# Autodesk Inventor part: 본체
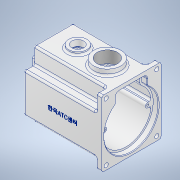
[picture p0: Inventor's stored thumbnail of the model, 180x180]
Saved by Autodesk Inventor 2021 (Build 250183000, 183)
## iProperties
Created: 2022-08
Part Number: 본체
Material: 알루미늄 6061
Document SubType Name: Modeling
Designer: Owner
Density: 2.7 g/cm^3
Appearance: 알루미늄 - 평지
Mass: 1404.44 g
Surface Area: 1171.86 cm^2
Volume: 520.162 cm^3
Author: Owner
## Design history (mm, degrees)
sketch "스케치1"
  geometry: L1 (-55, 49)-(55, 49); L2 (55, 49)-(55, -49); L3 (55, -49)-(-55, -49); L4 (-55, -49)-(-55, 49); L5 (-55, 49)-(55, -49); L6 (55, 49)-(-55, -49); 1 further point
  constraints: 12 end point, 2 midpoint, 2 parallel, 1 horizontal, 1 perpendicular
  dimensions: "d0" = 98 distance of L1.end L2.end; "d1" = 110 distance of L1.start L1.end
extrude "돌출1" new body sketch "스케치1" distance "d2" = 10; taper "d3" = 0 deg
sketch "스케치2"
  geometry: L1 (-49, 55)-(-49, -55) reference; L2 (-49, -55)-(49, -55) reference; L3 (49, -55)-(49, 55) reference; L4 (49, 55)-(-49, 55) reference; L5 (-33, -55)-(33, -55); L6 (33, -55)-(33, -38); L7 (33, 55)-(-33, 55); L8 (-33, 55)-(-33, 28); L9 (-33, -55)-(33, 55); L10 (33, -55)-(-33, 55); L11 (-49, -38)-(-33, -38); L12 (49, -38)-(49, 28); L13 (49, 28)-(33, 28); L14 (-49, 28)-(-49, -38); L15 (-49, -38)-(49, 28); L16 (49, -38)-(-49, 28); L17 (-33, 28)-(-49, 28); L18 (33, 28)-(-33, 28); L19 (-33, -38)-(-33, -55); L20 (33, -38)-(49, -38); L21 (-33, 28)-(-33, -38); L22 (33, 28)-(33, 55); L23 (33, -38)-(33, 28); L24 (-33, -38)-(33, -38); 11 further points
  constraints: 40 end point, 20 parallel, 7 midpoint, 6 perpendicular, 4 horizontal, 2 point on line
  dimensions: "d4" = 66 distance of L7.start L7.end; "d6" = 17 distance between parallel lines of L2 L11; "d7" = 27 distance between parallel lines of L4 L13
extrude "돌출2" join sketch "스케치2" distance "d8" = 120; taper "d9" = 0 deg
sketch "스케치4"
  geometry: L1 (-49, -55)-(49, -55) reference; L2 (-23, 30.143)-(-23, 45); L3 (-23, 45)-(23, 45); L4 (23, 45)-(23, 30.143); L5 (0, 0)-(0, 19.376); A1 r 42 centre (0, -5) between (-23, 30.143) and (23, 30.143)
  constraints: 8 end point, 2 perpendicular, 2 point on circle, 2 vertical, 1 centre point, 1 vertical alignment, 1 other
  dimensions: "d14" = 50 distance from line of L1 A1.centre; "d15" = 46 distance of L2.end L3.end; "d16" = 50 distance from line of A1.centre L3; "d17" = 84 diameter of A1
extrude "돌출4" cut sketch "스케치4" distance "d18" = 121; taper "d19" = 0 deg
fillet "모깎기1" dims "d20" = 6
sketch "스케치5"
  geometry: L1 (-23, 33.249)-(-23, 45) reference; L2 (-23, 45)-(23, 45) reference; L3 (23, 45)-(23, 33.249) reference; L4 (-26, 48)-(-26, 33.249); L5 (26, 33.249)-(26, 48); L6 (26, 48)-(-26, 48); A1 r 6 centre (29, 33.249) between (23, 33.249) and (25.375, 28.468) reference; A2 r 42 centre (0, -5) between (-25.375, 28.468) and (25.375, 28.468) reference; A3 r 6 centre (-29, 33.249) between (-25.375, 28.468) and (-23, 33.249) reference; A4 r 3 centre (-29, 33.249) between (-27.187, 30.859) and (-26, 33.249); A5 r 45 centre (0, -5) between (-27.187, 30.859) and (27.188, 30.859); A6 r 3 centre (29, 33.249) between (26, 33.249) and (27.188, 30.859); 1 further point
  constraints: 6 end point, 6 point on circle, 3 centre point, 5 other
  dimensions: "d21" = 3 distance between parallel lines of L1 L4
extrude "돌출5" cut sketch "스케치5" distance "d22" = 9; taper "d23" = 0 deg
sketch "스케치6"
  geometry: A1 r 42 centre (0, -5) between (-25.375, 28.468) and (25.375, 28.468) reference; A2 r 15 centre (0, -25) between (-8.978, -12.984) and (8.978, -12.984); A3 r 21 centre (0, 6) between (8.978, -12.984) and (-8.978, -12.984); 1 further point
  constraints: 4 point on circle, 2 centre point, 2 vertical alignment
  dimensions: "d24" = 30 diameter of A2; "d25" = 20 distance of A2.centre A1.centre; "d26" = 42 diameter of A3; "d27" = 11 distance of A1.centre A3.centre
extrude "돌출6" join sketch "스케치6" distance "d28" = 7; taper "d29" = 0 deg
sketch "스케치8"
  geometry: A1 r 15 centre (0, -25) between (-8.978, -12.984) and (8.978, -12.984) reference; 2 further points
  constraints: 1 coincident
hole "구멍1" sketch "스케치8" at (0, -25) diameter "d30" = 19; stored, may be unused: countersink angle "d34" = 90 deg, drill point angle "d36" = 0 deg; dims "d31" = 12, "d32" = 22, "d33" = 7, "d35" = 10
sketch "스케치10"
  geometry: A1 r 21 centre (0, 6) between (8.978, -12.984) and (-8.978, -12.984) reference; 2 further points
  constraints: 1 coincident
hole "구멍3" sketch "스케치10" at (0, 6) diameter "d44" = 35; stored, may be unused: countersink angle "d48" = 90 deg, drill point angle "d50" = 0 deg; dims "d45" = 12, "d46" = 32, "d47" = 8.3, "d49" = 10
sketch "스케치11"
  geometry: L1 (0, -5)-(36, -5); L2 (0, -5)-(-36, -5); L3 (-35.777, -1)-(-41.809, -1); L4 (-35.777, -9)-(-41.809, -9); L5 (35.777, -1)-(41.809, -1); L6 (35.777, -9)-(41.809, -9); A1 r 42 centre (0, -5) between (-25.375, 28.468) and (25.375, 28.468) reference; A2 r 45 centre (0, -5) between (-27.187, 30.859) and (27.188, 30.859) reference; A3 r 36 centre (0, -5) between (36, -5) and (-36, -5); A4 r 4 centre (36, -5) between (36, -1) and (36, -9); A5 r 4 centre (-36, -5) between (-36, -9) and (-36, -1); 1 further point
  constraints: 14 point on circle, 12 end point, 5 point on line, 4 tangent, 3 centre point, 3 coincident, 3 horizontal, 2 parallel
  dimensions: "d51" = 72 diameter of A3; "d52" = 8 diameter of A5; "d53" = 8 diameter of A4
extrude "돌출7" join sketch "스케치11" stored distance "d54" = 121; taper "d55" = 0 deg
sketch "스케치12"
  geometry: A1 r 4 centre (36, -5) between (36, -1) and (36, -9) reference; 2 further points
  constraints: 1 coincident
hole "구멍4" sketch "스케치12" at (36, -5) diameter "d56" = 3.45873; stored, may be unused: countersink angle "d60" = 90 deg, drill point angle "d62" = 118 deg; dims "d57" = 7, "d58" = 32, "d59" = 8.3, "d61" = 9
sketch "스케치13"
  geometry: A1 r 4 centre (-36, -5) between (-36, -9) and (-36, -1) reference; 2 further points
  constraints: 1 coincident
hole "구멍5" sketch "스케치13" at (-36, -5) diameter "d63" = 3.45873; stored, may be unused: countersink angle "d67" = 90 deg, drill point angle "d69" = 118 deg; dims "d64" = 7, "d65" = 32, "d66" = 8.3, "d68" = 9
sketch "스케치15"
  geometry: L1 (-27, -21)-(27, -21); L2 (27, -21)-(27, 33); L3 (27, 33)-(-27, 33); L4 (-27, 33)-(-27, -21); L5 (-27, -21)-(27, 33); L6 (27, -21)-(-27, 33); L7 (-49, -55)-(-33, -55) reference; 3 further points
  constraints: 12 end point, 3 midpoint, 2 parallel, 1 horizontal, 1 perpendicular, 1 vertical alignment
  dimensions: "d71" = 54 distance of L2.end L3.end; "d72" = 54 distance of L1.end L2.end; "d73" = 61 distance from line of L7 point (0, 6)
extrude "돌출8" join sketch "스케치15" distance "d74" = 7; taper "d75" = 0 deg
sketch "스케치16"
  geometry: A1 r 21 centre (0, 6) between (8.978, -12.984) and (-8.978, -12.984) reference; 2 further points
  constraints: 1 coincident
hole "구멍6" sketch "스케치16" at (0, 6) diameter "d76" = 28; stored, may be unused: countersink angle "d80" = 90 deg, drill point angle "d82" = 0 deg; dims "d77" = 7, "d78" = 32, "d79" = 8.3, "d81" = 52.5
fillet "모깎기2" dims "d70" = 0.3
chamfer "모따기1" distance "d83" = 0.8; stored, may be unused: second distance "d84" = 2, angle "d85" = 30 deg
sketch "스케치17"
  geometry: L1 (0, 98)-(0, 0) reference; C1 r 22.5 at (-40, 49); 2 further points
  constraints: 1 centre point, 1 horizontal alignment, 1 midpoint
  dimensions: "d86" = 45 diameter of C1; "d87" = 40 distance of point (0, 49) C1.centre
extrude "돌출9" join sketch "스케치17" distance "d88" = 10; taper "d89" = 0 deg
sketch "스케치18"
  geometry: L1 (0, 98)-(0, 0) reference; C1 r 22.5 at (-40, 49) reference; C2 r 15 at (-89, 49); 2 further points
  constraints: 1 centre point, 1 horizontal alignment, 1 midpoint
  dimensions: "d90" = 30 diameter of C2; "d91" = 49 distance of C2.centre C1.centre
extrude "돌출10" join sketch "스케치18" distance "d92" = 5; taper "d93" = 0 deg
sketch "스케치19"
  geometry: C1 r 22.5 at (0, 0) reference; 2 further points
  constraints: 1 coincident
hole "구멍7" sketch "스케치19" at (0, 0) diameter "d94" = 33.376; stored, may be unused: countersink angle "d98" = 90 deg, drill point angle "d100" = 0 deg; dims "d95" = 70, "d96" = 32, "d97" = 8.3, "d99" = 77.3
sketch "스케치21"
  geometry: C1 r 15 at (32, 23) reference; 2 further points
  constraints: 1 coincident
hole "구멍8" sketch "스케치21" at (32, 23) diameter "d101" = 20; stored, may be unused: countersink angle "d105" = 90 deg, drill point angle "d107" = 0 deg; dims "d102" = 70, "d103" = 30, "d104" = 5, "d106" = 77.3
fillet "모깎기3" dims "d108" = 3
fillet "모깎기4" dims "d109" = 3
fillet "모깎기5" dims "d110" = 3
fillet "모깎기6" dims "d111" = 3
fillet "모깎기7" dims "d112" = 3
fillet "모깎기8" dims "d113" = 3
chamfer "모따기3" distance "d118" = 1; stored, may be unused: second distance "d119" = 2, angle "d120" = 45 deg
fillet "모깎기10" dims "d121" = 3
sketch "스케치22"
  geometry: L1 (46, 55)-(-46, 55) reference; L2 (-49, 52)-(-49, -52) reference; 2 further points
  dimensions: "d129" = 7 distance from line of L1 point (-42, 48); "d130" = 7 distance from line of L2 point (-42, 48)
hole "구멍9" sketch "스케치22" at (-42, 48) diameter "d122" = 7; stored, may be unused: countersink angle "d126" = 90 deg, drill point angle "d128" = 0 deg; dims "d123" = 70, "d124" = 32, "d125" = 8.3, "d127" = 77.3
fillet "모깎기11" dims "d137" = 3
fillet "모깎기12" dims "d138" = 3
sketch "스케치23"
  geometry: L1 (-130, 104)-(-130, 83) reference; L2 (-13, 80)-(-127, 80) reference; 2 further points
  constraints: 1 other
  dimensions: "d139" = 65 distance from line of L1 point (-65, 47); "d140" = 33 distance from line of L2 point (-65, 47)
feature "엠보싱1" sketch "스케치23" dims "d141" = 0.5, "d142" = 0
fillet "모깎기13" dims "d143" = 6
fillet "모깎기14" dims "d144" = 3
chamfer "모따기4" distance "d145" = 1; stored, may be unused: second distance "d146" = 2, angle "d147" = 45 deg
fillet "모깎기15" dims "d148" = 3
fillet "모깎기16" dims "d149" = 3
node "솔리드1"
pattern_linear "직사각형 패턴1" dims "d133" = 84, "d136" = 96
feature "A9D066F2-1C7D-4E18-AEED-F7BC21143FA4" dims "d30" = 19, "d31" = 12, "d32" = 22, "d33" = 7, "d34" = 90 deg, "d35" = 10, "d36" = 0
